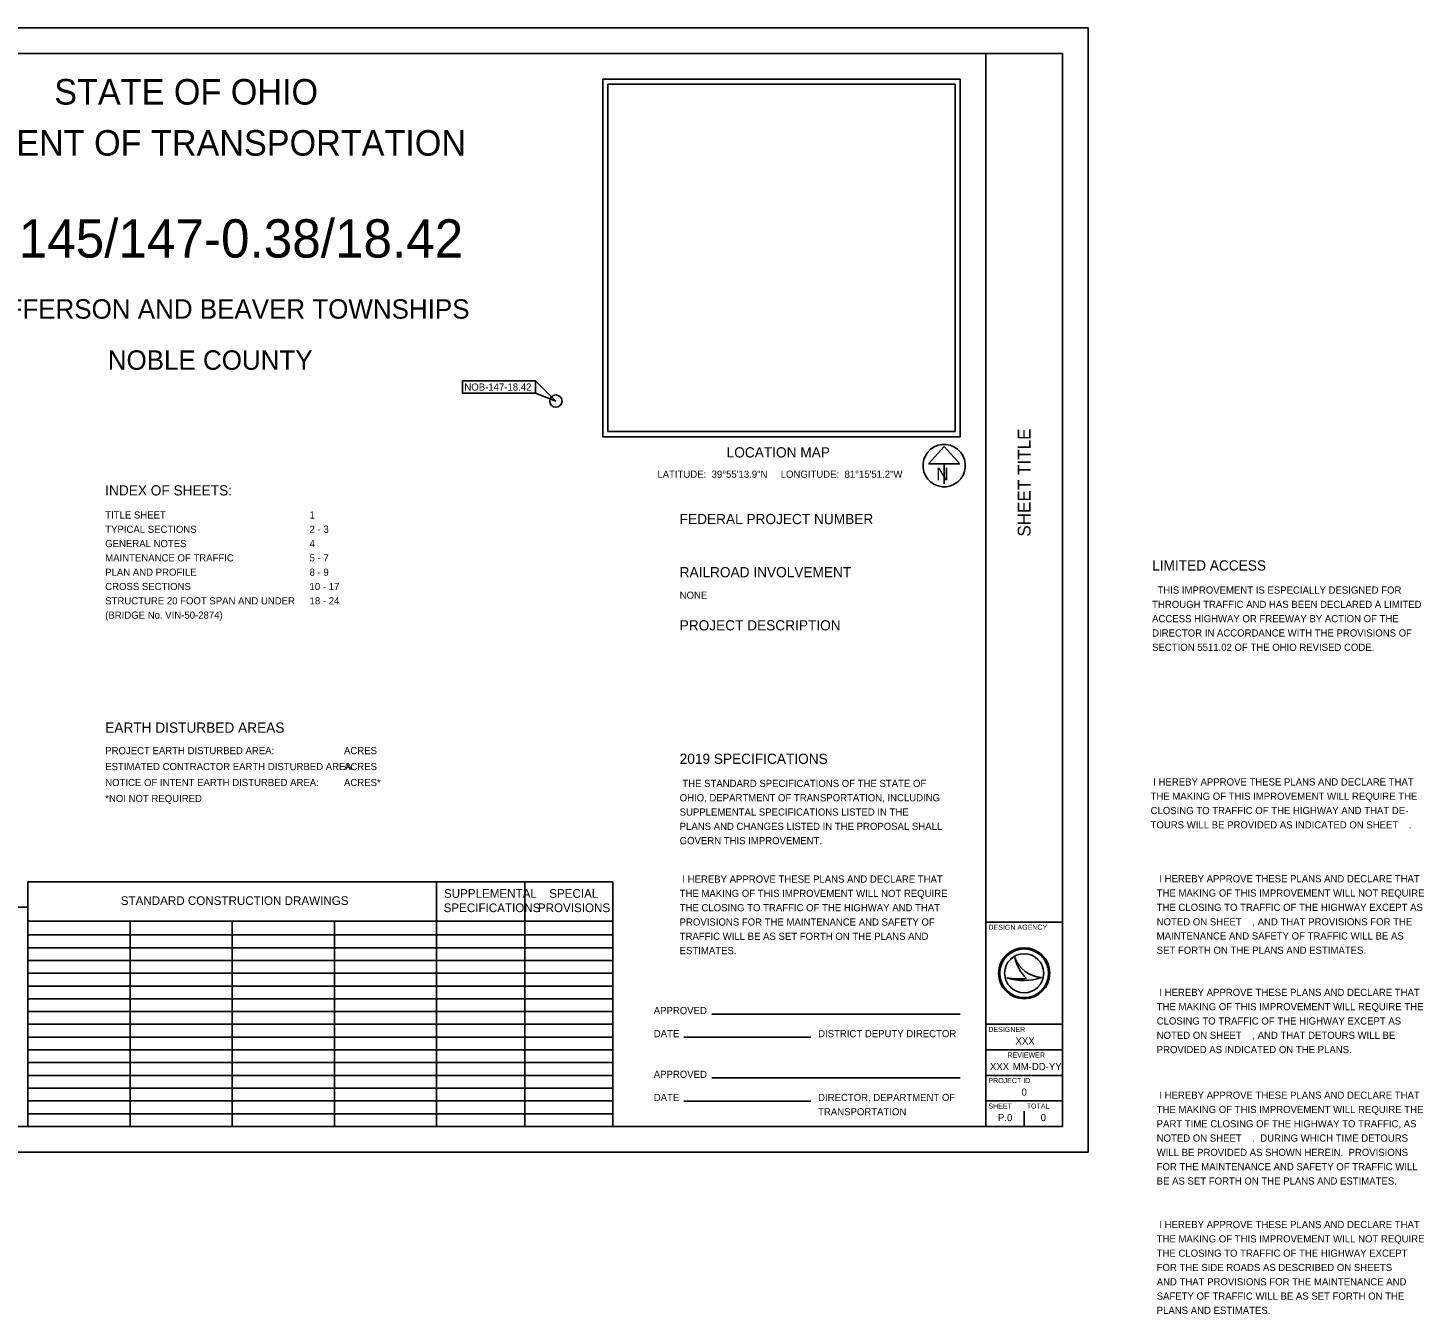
# Model space of a CAD drawing. Extents: x -10.5 to 40.6, y -3.2 to 22.
# Drawn here: x 13.25 to 40.58, y -3.17 to 22 of the extents above; entities that cross this region are included whole.
import ezdxf

# ---------------------------------------------------------------- set-up
doc = ezdxf.new("R2010")
doc.units = 0
for name, color, linetype in [('SH_Border', 7, 'Continuous'), ('SH_Cut_Line', 7, 'Continuous'), ('SH_Data', 7, 'Continuous'), ('SH_Text', 7, 'Continuous')]:
    doc.layers.add(name, color=color, linetype=linetype)

msp = doc.modelspace()

# ---------------------------------------------------------------- linework, layer by layer
at = {"layer": 'SH_Border'}
for p, q in [((32, 0.5), (32, 21.5)), ((32, 4.5), (33.5, 4.5)), ((32, 2.5), (33.5, 2.5)), ((32, 2), (33.5, 2)), ((32, 1.5), (33.5, 1.5)), ((32, 1), (33.5, 1))]:
    msp.add_line(p, q, dxfattribs=at)
msp.add_lwpolyline([(1.5, 21.5), (33.5, 21.5), (33.5, 0.5), (1.5, 0.5)], close=True, dxfattribs=at)
at = {"layer": 'SH_Cut_Line'}
msp.add_lwpolyline([(0, 0), (34, 0), (34, 22), (0, 22)], close=True, dxfattribs=at)
at = {"layer": 'SH_Data'}
for p, q in [((24.5, 21), (31.5, 21)), ((24.5, 21), (24.5, 14)), ((24.6, 20.9), (24.6, 14.1)), ((24.6, 20.9), (31.4, 20.9)), ((31.4, 20.9), (31.4, 14.1)), ((31.5, 21), (31.5, 14)), ((24.5, 14), (31.5, 14)), ((24.6, 14.1), (31.4, 14.1)), ((24.6, 14.1), (24.6, 14.1)), ((31.185, 13.809), (30.877, 13.468)), ((31.492, 13.468), (31.185, 13.809)), ((30.877, 13.468), (31.492, 13.468)), ((31.185, 13.468), (31.185, 13.081)), ((31.185, 13.435), (31.185, 13.435)), ((31.185, 13.435), (31.185, 13.435)), ((13.25, 5.292), (24.7, 5.292)), ((13.25, 0.5), (13.25, 5.292)), ((21.25, 0.5), (21.25, 5.292)), ((22.975, 0.5), (22.975, 5.292)), ((24.7, 0.5), (24.7, 5.292)), ((8.45, 4.792), (13.25, 4.792)), ((13.25, 0.5), (13.25, 4.521)), ((13.25, 4.521), (24.7, 4.521)), ((15.25, 0.5), (15.25, 4.521)), ((17.25, 0.5), (17.25, 4.521)), ((19.25, 0.5), (19.25, 4.521)), ((13.25, 4.25), (24.7, 4.25)), ((13.25, 4), (24.7, 4)), ((13.25, 3.75), (24.7, 3.75)), ((32.567, 3.81), (32.567, 3.81)), ((13.25, 3.5), (24.7, 3.5)), ((32.417, 3.41), (32.417, 3.41)), ((32.75, 3.5), (32.75, 3.5)), ((33.087, 3.419), (33.087, 3.419)), ((13.25, 3.25), (24.7, 3.25)), ((13.25, 3), (24.7, 3)), ((13.25, 2.75), (24.7, 2.75)), ((13.25, 2.5), (24.7, 2.5)), ((26.635, 2.7), (31.5, 2.7)), ((13.25, 2.25), (24.7, 2.25)), ((26.091, 2.248), (28.576, 2.248)), ((13.25, 2), (24.7, 2)), ((13.25, 1.75), (24.7, 1.75)), ((13.25, 1.5), (24.7, 1.5)), ((26.635, 1.452), (31.5, 1.452)), ((13.25, 1.25), (24.7, 1.25)), ((13.25, 1), (24.7, 1)), ((26.091, 0.999), (28.576, 0.999)), ((13.25, 0.75), (24.7, 0.75)), ((32.375, 0.675), (32.375, 0.675)), ((32.75, 0.5), (32.75, 0.8))]:
    msp.add_line(p, q, dxfattribs=at)
for radius in [0.5, 0.477, 0.477, 0.382]:
    msp.add_circle((32.75, 3.5), radius, dxfattribs=at)
for centre, radius, start, end in [((31.185, 13.435), 0.415, 129.7798, 129.7633), ((33.116, 3.998), 0.58, 198.9257, 198.9319), ((33.347, 3.97), 0.796, 191.6379, 191.6421), ((33.116, 3.998), 0.58, 198.9319, 267.1657), ((33.347, 3.97), 0.796, 191.6421, 226.0947), ((32.739, 4.37), 1.013, 251.4576, 290.0832), ((32.648, 4.654), 1.266, 259.4964, 259.4995), ((32.739, 4.37), 1.013, 251.4527, 251.4576), ((32.648, 4.654), 1.266, 259.4995, 276.6672)]:
    msp.add_arc(centre, radius, start, end, dxfattribs=at)
at = {"layer": 'SH_Text'}
for points in [[(23.188, 15.092), (21.756, 15.092), (21.756, 14.852), (23.188, 14.852)], [(21.756, 15.092), (23.188, 15.092), (23.188, 14.854), (21.756, 14.854)], [(23.584, 14.698), (23.188, 15.092), (23.188, 14.852)]]:
    msp.add_lwpolyline(points, close=True, dxfattribs=at)
msp.add_circle((23.584, 14.698), 0.12, dxfattribs=at)

# ---------------------------------------------------------------- texts
at = {"layer": 'SH_Data'}
msp.add_text('SHEET TITLE', height=0.25, rotation=90, dxfattribs=at).set_placement((32.875, 12.044))
for s, height, p in [('N', 0.25, (31.029, 13.144)), (' I HEREBY APPROVE THESE PLANS AND DECLARE THAT', 0.14, (35.225, 7.174)), ('THE MAKING OF THIS IMPROVEMENT WILL REQUIRE THE', 0.14, (35.225, 6.894)), ('CLOSING TO TRAFFIC OF THE HIGHWAY AND THAT DE-', 0.14, (35.225, 6.614)), ('TOURS WILL BE PROVIDED AS INDICATED ON SHEET    .', 0.14, (35.225, 6.334)), (' I HEREBY APPROVE THESE PLANS AND DECLARE THAT', 0.14, (26.007, 5.273)), (' I HEREBY APPROVE THESE PLANS AND DECLARE THAT', 0.14, (35.344, 5.28)), ('THE MAKING OF THIS IMPROVEMENT WILL NOT REQUIRE', 0.14, (26.007, 4.993)), ('THE MAKING OF THIS IMPROVEMENT WILL NOT REQUIRE', 0.14, (35.344, 5)), ('THE CLOSING TO TRAFFIC OF THE HIGHWAY AND THAT', 0.14, (26.007, 4.713)), ('THE CLOSING TO TRAFFIC OF THE HIGHWAY EXCEPT AS', 0.14, (35.344, 4.72)), ('PROVISIONS FOR THE MAINTENANCE AND SAFETY OF', 0.14, (26.007, 4.433)), ('DESIGN AGENCY', 0.1, (32.05, 4.35)), ('NOTED ON SHEET    , AND THAT PROVISIONS FOR THE', 0.14, (35.344, 4.437)), ('TRAFFIC WILL BE AS SET FORTH ON THE PLANS AND', 0.14, (26.007, 4.153)), ('MAINTENANCE AND SAFETY OF TRAFFIC WILL BE AS', 0.14, (35.344, 4.16)), ('ESTIMATES.', 0.14, (26.007, 3.873)), ('SET FORTH ON THE PLANS AND ESTIMATES.', 0.14, (35.344, 3.88)), (' I HEREBY APPROVE THESE PLANS AND DECLARE THAT', 0.14, (35.344, 3.056)), ('THE MAKING OF THIS IMPROVEMENT WILL REQUIRE THE', 0.14, (35.344, 2.776)), ('CLOSING TO TRAFFIC OF THE HIGHWAY EXCEPT AS', 0.14, (35.344, 2.496)), ('DESIGNER', 0.1, (32.05, 2.35)), ('XXX', 0.14, (32.581, 2.105)), ('NOTED ON SHEET    , AND THAT DETOURS WILL BE', 0.14, (35.344, 2.216)), ('REVIEWER', 0.1, (32.422, 1.85)), ('PROVIDED AS INDICATED ON THE PLANS.', 0.14, (35.344, 1.936)), ('XXX', 0.14, (32.081, 1.605)), ('MM-DD-YY', 0.14, (32.527, 1.605)), ('PROJECT ID', 0.1, (32.05, 1.35)), ('0', 0.14, (32.698, 1.105)), (' I HEREBY APPROVE THESE PLANS AND DECLARE THAT', 0.14, (35.344, 1.044)), ('SHEET', 0.1, (32.05, 0.85)), ('TOTAL', 0.1, (32.8, 0.85)), ('THE MAKING OF THIS IMPROVEMENT WILL REQUIRE THE', 0.14, (35.344, 0.764)), ('P.0', 0.14, (32.238, 0.605)), ('0', 0.14, (33.073, 0.605)), ('PART TIME CLOSING OF THE HIGHWAY TO TRAFFIC, AS', 0.14, (35.344, 0.484)), ('NOTED ON SHEET    .  DURING WHICH TIME DETOURS', 0.14, (35.344, 0.204)), ('WILL BE PROVIDED AS SHOWN HEREIN.  PROVISIONS', 0.14, (35.344, -0.076)), ('FOR THE MAINTENANCE AND SAFETY OF TRAFFIC WILL', 0.14, (35.344, -0.356)), ('BE AS SET FORTH ON THE PLANS AND ESTIMATES.', 0.14, (35.344, -0.636)), (' I HEREBY APPROVE THESE PLANS AND DECLARE THAT', 0.14, (35.344, -1.488)), ('THE MAKING OF THIS IMPROVEMENT WILL NOT REQUIRE', 0.14, (35.344, -1.768)), ('THE CLOSING TO TRAFFIC OF THE HIGHWAY EXCEPT', 0.14, (35.344, -2.048)), ('FOR THE SIDE ROADS AS DESCRIBED ON SHEETS    ', 0.14, (35.344, -2.328)), ('AND THAT PROVISIONS FOR THE MAINTENANCE AND', 0.14, (35.344, -2.608)), ('SAFETY OF TRAFFIC WILL BE AS SET FORTH ON THE', 0.14, (35.344, -2.888)), ('PLANS AND ESTIMATES.', 0.14, (35.344, -3.168))]:
    msp.add_text(s, height=height, dxfattribs=at).set_placement(p)
at = {"layer": 'SH_Text'}
for s, height, p in [('STATE OF OHIO', 0.5, (13.766, 20.5)), ('DEPARTMENT OF TRANSPORTATION', 0.5, (9.753, 19.5)), ('NOB-145/147-0.38/18.42', 0.75, (10.563, 17.505)), ('JEFFERSON AND BEAVER TOWNSHIPS', 0.38, (12.238, 16.31)), ('NOBLE COUNTY', 0.38, (14.813, 15.31)), ('NOB-147-18.42', 0.14, (21.793, 14.902)), ('LOCATION MAP', 0.2, (26.927, 13.594)), ('LATITUDE:  39°55\'13.9"N     LONGITUDE:  81°15\'51.2"W', 0.14, (25.571, 13.196)), ('INDEX OF SHEETS:', 0.2, (14.763, 12.85)), ('TITLE SHEET', 0.14, (14.763, 12.399)), ('1', 0.14, (18.763, 12.399)), ('FEDERAL PROJECT NUMBER', 0.2, (26.007, 12.289)), ('TYPICAL SECTIONS', 0.14, (14.763, 12.119)), ('2 - 3', 0.14, (18.763, 12.119)), ('GENERAL NOTES', 0.14, (14.763, 11.839)), ('4', 0.14, (18.763, 11.839)), ('MAINTENANCE OF TRAFFIC', 0.14, (14.763, 11.559)), ('5 - 7', 0.14, (18.763, 11.559)), ('LIMITED ACCESS', 0.2, (35.255, 11.381)), ('PLAN AND PROFILE', 0.14, (14.763, 11.279)), ('8 - 9', 0.14, (18.763, 11.279)), ('RAILROAD INVOLVEMENT', 0.2, (26.007, 11.249)), ('CROSS SECTIONS', 0.14, (14.763, 10.999)), ('10 - 17', 0.14, (18.763, 10.999)), ('NONE', 0.14, (26.007, 10.829)), ('  THIS IMPROVEMENT IS ESPECIALLY DESIGNED FOR', 0.14, (35.255, 10.929)), ('STRUCTURE 20 FOOT SPAN AND UNDER', 0.14, (14.763, 10.719)), ('18 - 24', 0.14, (18.763, 10.719)), ('THROUGH TRAFFIC AND HAS BEEN DECLARED A LIMITED', 0.14, (35.255, 10.649)), ('(BRIDGE No. VIN-50-2874)', 0.14, (14.763, 10.439)), ('PROJECT DESCRIPTION', 0.2, (26.007, 10.209)), ('ACCESS HIGHWAY OR FREEWAY BY ACTION OF THE', 0.14, (35.255, 10.369)), ('DIRECTOR IN ACCORDANCE WITH THE PROVISIONS OF', 0.14, (35.255, 10.089)), ('SECTION 5511.02 OF THE OHIO REVISED CODE.', 0.14, (35.255, 9.809)), ('EARTH DISTURBED AREAS', 0.2, (14.763, 8.207)), ('PROJECT EARTH DISTURBED AREA:', 0.14, (14.763, 7.787)), ('     ACRES', 0.14, (19.177, 7.787)), ('2019 SPECIFICATIONS', 0.2, (26.007, 7.597)), ('ESTIMATED CONTRACTOR EARTH DISTURBED AREA:', 0.14, (14.763, 7.475)), ('     ACRES', 0.14, (19.177, 7.475)), ('NOTICE OF INTENT EARTH DISTURBED AREA:', 0.14, (14.763, 7.163)), ('     ACRES*', 0.14, (19.177, 7.163)), (' THE STANDARD SPECIFICATIONS OF THE STATE OF', 0.14, (26.007, 7.145)), ('*NOI NOT REQUIRED', 0.14, (14.763, 6.851)), ('OHIO, DEPARTMENT OF TRANSPORTATION, INCLUDING', 0.14, (26.007, 6.865)), ('SUPPLEMENTAL SPECIFICATIONS LISTED IN THE', 0.14, (26.007, 6.585)), ('PLANS AND CHANGES LISTED IN THE PROPOSAL SHALL', 0.14, (26.007, 6.305)), ('GOVERN THIS IMPROVEMENT.', 0.14, (26.007, 6.025)), ('STANDARD CONSTRUCTION DRAWINGS', 0.17, (15.067, 4.836)), ('SUPPLEMENTAL', 0.17, (21.393, 4.976)), ('SPECIAL', 0.17, (23.454, 4.976)), ('SPECIFICATIONS', 0.17, (21.387, 4.696)), ('PROVISIONS', 0.17, (23.232, 4.696)), ('APPROVED', 0.14, (25.5, 2.7)), ('DATE', 0.14, (25.5, 2.248)), ('DISTRICT DEPUTY DIRECTOR', 0.14, (28.717, 2.248)), ('APPROVED', 0.14, (25.5, 1.452)), ('DATE', 0.14, (25.5, 0.999)), ('DIRECTOR, DEPARTMENT OF', 0.14, (28.717, 0.999)), ('TRANSPORTATION', 0.14, (28.717, 0.719))]:
    msp.add_text(s, height=height, dxfattribs=at).set_placement(p)

doc.saveas('drawing.dxf')
